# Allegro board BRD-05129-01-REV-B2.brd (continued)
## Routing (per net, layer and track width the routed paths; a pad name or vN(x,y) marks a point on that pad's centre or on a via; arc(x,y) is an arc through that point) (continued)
PMOD1_IO4_HDA14: length 59.1
  TOP w0.13: C379.1 v1(17.25,15.03) 17.28,15 J2.7
  L10_SIG w0.102: v1(9.44,56.82) 8.66,56.03 8.48,56.03 4.89,52.43 4.89,48.68 7.87,45.69 7.87,42.32 7.23,41.68 7.23,40.05 7.59,39.7 7.59,37.22 7.2,36.83 7.2,29.91 10.69,26.42 10.69,26.11 10.54,25.97 10.03,25.97 9.88,25.82 9.88,25.61 10.03,25.46 10.54,25.46 10.69,25.31 10.69,24.57 10.66,24.54 10.66,20.79 10.84,20.62 10.84,20.41 10.67,20.25 10.67,20.04 10.82,19.89 11.03,19.89 11.19,20.05 11.4,20.05 11.55,19.9 11.55,19.69 11.39,19.53 11.39,19.32 11.54,19.17 11.75,19.17 11.91,19.33 12.12,19.33 12.27,19.18 12.27,18.97 12.11,18.81 12.11,18.6 12.26,18.45 12.47,18.45 12.63,18.61 12.84,18.61 12.99,18.46 12.99,18.25 12.83,18.09 12.83,17.88 12.98,17.73 13.19,17.73 13.35,17.9 13.56,17.9 13.92,17.53 14.78,17.53 15.86,16.45 16.11,16.45 16.41,16.75 16.66,16.75 16.84,16.57 16.84,16.32 16.54,16.02 16.54,15.77 17.25,15.06 v1(17.25,15.03)
  BOTTOM w0.13: R282.2 v1(9.44,56.82)
PMOD1_IO5_HDA15: length 56.9
  L10_SIG w0.102: v1(9.44,51.23) 9.98,50.69 9.98,50.1 12.14,47.94 12.14,44.75 13.04,43.85 13.04,40.25 21.8,31.49 21.8,30.97 21.66,30.83 21.51,30.83 21.36,30.68 21.36,30.47 21.51,30.32 21.66,30.32 21.8,30.17 21.8,26.1 23.55,24.35 23.8,24.35 23.95,24.5 24.2,24.5 24.38,24.32 24.38,24.07 24.23,23.92 24.23,23.67 24.41,23.49 24.66,23.49 24.81,23.64 25.06,23.64 25.24,23.46 25.24,23.21 25.09,23.06 25.09,22.81 25.27,22.63 25.52,22.63 25.88,22.99 26.13,22.99 26.31,22.81 26.31,22.56 25.96,22.2 25.96,21.95 27.35,20.55 27.35,11.03 v1(27.86,10.52)
  BOTTOM w0.13: R275.2 C373.1 v1(27.86,10.52) 27.43,10.52 27.22,10.31 J2.2 ; R277.2 v1(9.44,51.23)
PMOD1_IO6_HDA16_CC: length 55.9
  TOP w0.13: C375.1 v1(23.67,15.03)
  L10_SIG w0.102: v1(23.67,15.03) 23.15,15.55 23.15,19.97 22.07,21.05 22.07,21.31 22.2,21.44 22.2,21.69 22.03,21.87 21.77,21.87 21.64,21.74 21.39,21.74 21.21,21.91 21.21,22.17 21.34,22.3 21.34,22.55 21.16,22.73 20.91,22.73 20.78,22.6 20.53,22.6 20.35,22.78 20.35,23.03 20.48,23.16 20.48,23.41 20.3,23.59 20.05,23.59 19.92,23.46 19.66,23.46 16.91,26.21 16.91,34.51 13.08,38.34 12.83,38.34 12.64,38.16 12.39,38.16 12.21,38.34 12.21,38.59 12.4,38.77 12.4,39.03 12.22,39.21 11.96,39.21 11.78,39.02 11.53,39.02 11.35,39.2 11.35,39.45 11.53,39.64 11.53,39.89 10.99,40.43 10.99,47.69 8.89,49.8 8.89,51.53 9.09,51.74 9.75,51.74 9.99,51.97 9.99,52.82 v1(9.42,53.39)
  BOTTOM w0.13: v1(23.67,15.03) 23.67,11.62 J2.4 ; R279.2 v1(9.42,53.39)
PMOD1_IO7_HDA17: length 56.2
  TOP w0.13: C378.1 v1(21,15.03)
  L10_SIG w0.102: v1(21,15.03) 20.53,15.5 20.53,18.55 19.88,19.21 19.88,19.46 20.03,19.62 20.03,19.87 19.86,20.05 19.6,20.05 19.44,19.89 19.19,19.89 19.01,20.07 19.01,20.32 19.17,20.48 19.17,20.73 18.99,20.91 18.74,20.91 18.58,20.75 18.33,20.75 18.15,20.93 18.15,21.18 18.31,21.34 18.31,21.6 18.13,21.77 17.88,21.77 17.72,21.62 17.47,21.62 13.36,25.73 12.8,25.73 8.18,30.34 8.18,36.15 9.34,37.31 9.34,42.26 9.12,42.49 9.12,46.93 7.35,48.7 7.35,52.4 9.44,54.49 v1(9.44,54.53)
  BOTTOM w0.13: J2.6 21.1,11.6 21.1,14.93 v1(21,15.03) ; R281.2 v1(9.44,54.53)
PMOD1_IO8_HDA18: length 57.8
  TOP w0.13: J2.8 15.97,11.62 15.97,14.14 15.92,14.19 v1(15.92,15.03) C380.1
  L10_SIG w0.102: v1(9.44,58.09) 7.87,56.51 7.53,56.51 5.88,54.86 5.88,54.34 4.24,52.7 4.24,45.92 4.44,45.72 4.44,42.06 4.14,41.75 4.14,36.29 4.01,36.17 4.01,34.26 4.62,33.65 4.62,29.18 9.4,24.39 9.4,20.64 15.01,15.03 v1(15.92,15.03)
  BOTTOM w0.13: R283.2 v1(9.44,58.09)
PMOD_3V3: length 12.8
  TOP w0.381: C238.1 v1(12.3,17.06) ; U42.1 v1(3.41,10.55) ; C376.1 v1(12.3,16.18)
  L05_SIG w0.381: J2.11 13.04,12.01 ; J2.11 11.36,12.01 ; J2.11 11.36,13.69 ; J2.11 13.04,13.69 ; J2.12 13.04,11.15 ; J2.12 11.36,11.15 ; J2.12 13.04,9.47 ; J2.12 11.36,9.47
  BOTTOM w0.381: v1(3.41,10.55) 3.38,10.52 C387.1
PMOD_PWR_EN: length 1.9
  TOP w0.381: U42.4 v1(5.31,14.94)
  BOTTOM w0.381: R167.1 5.35,14.97 v1(5.31,14.94)
PMOD_PWR_FLT_B: length 1.9
  TOP w0.381: U42.3 v1(5.31,10.55)
  BOTTOM w0.381: v1(5.31,10.55) 5.35,10.52 R166.2
PMU_RESET_OUT_B: length 34.3
  L10_SIG w0.102: v1(31.98,44.33) 32.88,44.33 33.27,43.94 35.4,43.94 36.6,42.75 37.41,42.75 38.19,41.97 38.19,41.36 38.68,40.88 38.68,33.83 33.99,29.14 J51.2
  BOTTOM w0.13: v1(31.98,44.33) 31.98,43.75 32.18,43.56 U19.16
PS_1V2: length 40.1
  TOP w0.381: v1(24.94,80.44) 24.84,80.54 v1(24.84,82.24) 24.84,83.51 26.76,85.44 v1(27.68,85.44) ; v2(25.83,90.98) 25.83,88.57 26.93,87.47 v1(27.68,87.47) ; C285.1 63.78,86.09 63.98,86.29 v1(63.98,87.07)
  BOTTOM w0.178: v1(24.84,82.24) U5.12
  BOTTOM w0.203: v1(68.4,92.63) 68.28,92.51 U43.33 ; U43.12 59.4,93.31 v1(59.14,93.57) ; U43.43 66.38,87.7 67.22,86.87 v1(68.22,86.87) ; U43.28 66.38,95.57 v1(66,95.96) ; v1(59.2,90.19) 59.51,90.51 U43.5 ; v1(59.54,95.96) 59.54,95.62 60.2,94.96 U43.15 ; U43.21 v1(63.58,95.96)
  BOTTOM w0.254: R21.1 v1(24.94,80.44) ; U43.49 v1(63.98,87.07)
  BOTTOM w0.381: C290.1 70.13,85.87 69.7,86.3 69.21,86.3 68.65,86.87 v1(68.22,86.87) ; C283.1 59.95,96.37 v1(59.54,95.96) ; C284.1 C295.1 59.15,90.24 v1(59.2,90.19) ; C292.1 63.53,96.01 v1(63.58,95.96) ; v1(66,95.96) 66.26,96.21 66.39,96.21 66.83,96.65 C289.1 ; C291.1 C296.1 69.79,93.19 68.96,93.19 v1(68.4,92.63) ; v1(59.14,93.57) 59.08,93.57 57.96,94.69 C286.1
  vias: v1(27.68,86.45)
PS_1V2_FB: length 2.8
  BOTTOM w0.203: R21.2 26.53,81.56 26.36,81.74 U5.10
  BOTTOM w0.254: R21.2 R26.1
PS_1V8: length 79.1
  TOP w0.178: v1(49.47,26.19) 49.17,25.88 U25.6
  TOP w0.254: U94.B5 v1(110,103.04) ; v1(68.37,87.9) 68.15,87.68 67.01,87.68 66.41,88.28 66.17,88.28 66.03,88.41 U98.40 ; v1(60.31,87.53) 60.31,88.13 60.85,88.66 U98.31 ; U98.25 59.55,91.76 58.79,92.52 v1(58.43,92.52) ; v1(29.59,25.38) U16.2
  TOP w0.381: v1(53.56,88.42) R543.1 R542.1 ; R545.1 59.96,83.97 v1(58.63,83.97) 58.63,84.68 R544.1 ; C623.1 C640.1 58.3,92.65 v1(58.43,92.52) ; v1(68.37,87.9) C624.1 C622.1 ; v1(60.31,87.53) 60.27,87.57 C633.1 58.89,87.57 C632.1 ; R548.1 R546.1 53.72,91.97 v1(53.6,92.1) ; R536.1 55.4,98.69 v1(55.42,98.71) ; C92.1 42.85,27.16 v1(43.21,27.52) ; v1(55.93,95.93) 56.41,95.45 R537.1 ; v1(60.11,79.46) R547.1 60.79,81.93 R541.1 ; C631.1 v1(70.13,85.04) ; U94.A5 v1(106.11,102.27)
  L05_SIG w0.508: v1(58.63,83.97) 59.29,83.31 60.76,83.31 63.18,80.9 63.18,79.22 62.57,78.61 60.96,78.61 v1(60.11,79.46)
  BOTTOM w0.178: v1(43.21,27.52) 43.52,27.22 U64.6 ; U22.2 v1(40.27,28.86) ; U22.12 37.21,29.26 v1(36.9,29.56) ; v1(37.35,30.48) 37.6,30.48 37.99,30.09 U22.13
  BOTTOM w0.254: v1(45,80.41) 44.75,80.41 44.37,80.04 U37.14 ; U37.11 42.87,80.23 v1(42.77,80.34) ; R530.1 39.29,43.09 v1(39.59,42.78) ; U37.32 v1(41.87,73.71) ; v1(32.13,36.48) R449.1 32.14,37.11 R450.1 33.88,37.11 R451.1 v1(33.89,36.46) ; v1(5.05,89.38) 4.65,88.99 U13.10 ; R448.1 v1(33.31,47.06) ; R447.1 v1(34.2,47.06) ; U37.30 v1(42.87,73.71) ; C275.1 40.13,78.79 v1(40.15,78.76) 40.2,78.71 U37.8 ; C277.1 43.18,72.52 43.87,73.21 v1(43.87,73.71) U37.28 ; R683.1 v1(117.55,90.63) ; U13.1 4.65,85.72 v1(5.05,85.32)
  BOTTOM w0.381: R48.1 5.43,82.58 v1(5.74,82.27) ; C81.1 40.3,28.89 v1(40.27,28.86) ; C612.1 57.71,76.94 ; 58.72,76.94 R522.1 59.28,76.39 ; v1(3.3,82.22) 3.65,82.57 R47.1 R49.1 ; C276.1 41.36,73.2 v1(41.87,73.71) ; R515.1 v1(112.92,108.76) ; C329.1 29.45,25.52 v1(29.59,25.38) ; R45.1 v1(40.05,25.19) ; C600.1 v1(106.11,102.27) ; R46.1 v1(1.68,92.25) ; R516.1 v1(108.74,101) ; C91.1 49.7,25.39 49.7,25.96 v1(49.47,26.19) ; R210.1 v1(44.2,70.79) ; C50.1 v1(5.63,91.23)
  vias: v1(27.17,90.45) v1(27.17,89.43) v1(27.17,88.41) v1(28.19,90.45) v1(28.19,89.43) v1(28.19,88.41) v1(29.31,19.91) v1(30.25,19.91) v1(31.16,29.51) v1(31.26,19.91) v1(32.41,19.91) v1(43.33,1.82) v1(44.62,1.82) v1(56.94,78.48) v1(56.94,77.21) v1(58.47,77.21) v1(70.58,84.25) v1(83.49,102.33) v1(83.49,101.49) v1(83.49,100.22) v1(83.49,98.95) v1(112.92,95.86) v1(113.64,96.88) v2(49.2,94.15)
PS_1V8_EN: length 1.6
  BOTTOM w0.13: U96.5 R521.2
PS_1V8_FB: length 4
  BOTTOM w0.13: R523.1 58.73,75.48 R522.2 C612.2 57.37,75.49 57.07,75.19 U96.4
PS_1V8_RS485: length 4.3
  TOP w0.381: v1(122.97,94.42) 122.9,94.35 U95.1 ; 114.52,94.62 C602.1 115,95.1
  BOTTOM w0.381: v1(114.32,94.62) 114.91,94.03 R519.1
  vias: v1(115.23,95.92)
PS_3V3: length 67.5
  TOP w0.381: v1(34.69,97.21) 34.39,96.91 C560.1 ; C64.1 v1(31.3,22.58) ; R549.1 56.83,98.35 v1(56.85,98.37) ; C574.1 31.73,100.04 v1(31.28,100.49) 30.88,100.09 C176.1 ; C589.1 6.13,65.68 v7(6.95,64.86) ; R538.1 v1(71.78,91.84) ; v1(35.69,28.4) 35.44,28.15 C53.1 ; R54.1 v1(28.45,20.86) ; R256.2 v1(34.5,25.66) ; v1(28.49,93) 28.88,93.39 C561.1 ; C559.1 v1(27.21,97.21)
  L10_SIG w0.381: J24.11 79.85,114.37 ; J24.11 78.86,114.03 ; J24.11 80.18,115.35 ; J24.11 77.88,114.37 ; J24.11 77.54,115.35 ; J24.13 69.13,114.37 ; J24.13 66.83,115.35 ; J24.13 67.16,114.37 ; J24.13 69.46,115.35 ; J24.13 68.14,114.03
  BOTTOM w0.203: U43.44 65.98,87.55 67.11,86.43 67.11,86.18 ; v1(68.35,93.47) 68.19,93.31 U43.31 ; U43.37 68.01,90.91 v1(68.23,91.13) ; U43.16 v1(61.58,95.96)
  BOTTOM w0.254: 67.11,86.18 v1(67.09,86.18) ; v1(35.44,22.81) 35.15,22.52 U15.1 ; C303.1 C298.1 60.99,86.73 v1(61.33,87.07) 61.58,87.32 U43.55 ; U38.22 v1(34.69,97.21) ; C561.1 28.88,93.39 v1(28.49,93) ; C5.1 8.81,55.02 8.81,56.38 8.62,56.58 R1.1 ; v1(31.28,100.49) 30.88,100.09 C176.1 ; v1(35.69,28.4) 35.15,27.85 U15.8 ; C559.1 v1(27.21,97.21)
  BOTTOM w0.381: R220.2 v1(71.78,87.9) ; v1(27.36,24.87) 27.61,24.61 R56.1 R55.1 ; C297.1 61.1,96.44 v1(61.58,95.96) ; 7.56,56.58 R1.1 8.12,57.13 ; 67.11,86.18 67.72,85.57 C299.1 ; R468.2 R469.2 v1(65.94,98.65) ; R429.1 v1(34.48,101.39) ; C300.1 69.95,90.52 68.99,90.52 68.38,91.13 v1(68.23,91.13) ; 60.99,75.41 R243.1 60.43,75.97 ; v1(68.35,93.47) 68.75,93.87 C304.1 ; R218.1 v1(71.78,86.88) ; 51.56,76.64 R521.1 52.12,76.09 ; R464.1 v1(36.19,91.37) ; U89.6 v7(6.95,64.86) ; R130.1 v1(37.49,93.68) ; R494.1 v1(1.84,66.46) ; R463.1 v1(37.49,92.54)
  vias: v1(5.61,58.75) v1(7.03,60.88) v1(7.03,59.86) v1(7.03,58.72) v1(7.41,57.83) v1(8.05,60.88) v1(8.05,59.86) v1(8.05,58.72) v1(9.06,60.4) v1(9.06,59.25) v1(20.67,66.01) v1(20.67,63.47) v1(21.84,66.04) v1(21.84,63.5) v1(23.11,66.04) v1(23.11,63.5) v1(25.45,47.65) v1(25.45,46.38) v1(26.72,47.65) v1(26.72,46.38) v1(27.99,47.65) v1(27.99,46.38) v1(51.74,77.72) v1(52.5,78.35) v1(52.5,77.08) v1(60.61,76.99) v1(61.37,77.63) v1(61.37,76.36) v1(71.38,98.51) v1(71.42,97.4) v2(7.29,61.9)
PS_3V3_FB: length 3.3
  TOP w0.381: R2.1 v1(7.36,55.68)
  BOTTOM w0.203: R2.1 v1(7.36,55.68)
  BOTTOM w0.381: R1.2 v1(7.36,55.68)
PS_3V3_MODE: length 4.2
  BOTTOM w0.203: U1.13 7.02,53.48 7.43,53.06 R4.2 R5.1
PS_3V3_RAMP: length 1.6
  BOTTOM w0.203: C5.2 7.25,54.83 7.05,55.03 U1.11
PS_ERROR_OUT_M2C: length 16.1
  TOP w0.127: TP38.1 9.06,64.31 v1(9.98,64.31)
  TOP w0.13: JA1.B24 v4(16.01,56.4)
  L05_SIG w0.102: v4(16.01,56.4) 15.36,55.75 12.29,55.75 11.64,56.4 11.64,57.64 11.17,58.11 11.17,59.36 10.68,59.85 10.68,63.61 v1(9.98,64.31)
PS_ERROR_STATUS_M2C: length 9.5
  TOP w0.127: TP39.1 v1(8.3,54.02)
  TOP w0.13: JA1.B25 v4(15.19,56.46)
  L12_SIG w0.102: v4(15.19,56.46) 14.54,55.82 10.84,55.82 10.06,55.05 8.86,55.05 8.3,54.49 v1(8.3,54.02)
PS_ETH_0V9: length 23.1
  TOP w0.254: U98.28 60.15,90.26 59.49,89.61 58.87,89.61 v1(58.49,89.22) ; 65.69,85.46 65.07,85.46 64.54,86 64.54,87.53 64.03,88.04 U98.36 ; v1(69.11,89.51) 69.11,89.84 68.45,90.49 67.59,90.49 67.33,90.76 U98.4
  TOP w0.381: C637.1 C627.1 69.81,89.42 69.73,89.51 v1(69.11,89.51) ; C629.1 57.95,91.76 58.25,91.46 58.29,91.46 58.45,91.3 v1(58.49,91.3) ; v1(58.49,89.22) 58.24,88.97 C636.1 57.76,90.04 C628.1 ; v2(50.85,93.26) 50.85,91.49 v1(52.5,89.84) ; C638.1 C630.1 v1(65.69,85.47)
  BOTTOM w0.381: 67.59,76.27 R6.1 68.15,75.71 ; C14.1 66.58,76.27
  vias: v1(65.81,77.76) v1(65.81,76.49) v1(67.34,76.49)
PS_ETH_0V9_EN: length 1.6
  BOTTOM w0.254: R243.2 U12.5
PS_ETH_0V9_FB: length 4.4
  BOTTOM w0.254: U12.4 66.28,74.51 C14.2 R6.2 R17.1
PS_GEM0_LED0_CA: length 8
  BOTTOM w0.13: R561.2 82.85,112.57 81.58,113.84 77.83,113.84 J24.12
PS_GEM0_LED1_CA: length 4.7
  BOTTOM w0.13: J24.14 63.56,115.35 63.17,115.74 R551.2
PS_GEM0_MDI_0_N: length 21.8
  TOP w0.089: U98.13 65.03,94.93 65.16,95.06 65.16,97.72 64.91,97.96 64.91,98.97 v3(64.64,99.24)
  L03_SIG w0.089: v3(64.64,99.24) 64.85,99.24 65.38,99.77 65.73,99.77 65.96,100 74.93,100 76.6,101.67 76.6,103.24 77.02,103.66 77.18,103.74 77.22,103.86 J24.2
PS_GEM0_MDI_0_P: length 21.8
  TOP w0.089: v3(65.42,99.24) 65.17,98.98 65.17,98.07 65.41,97.83 65.41,95.06 65.53,94.93 U98.12
  L03_SIG w0.089: v3(65.42,99.24) 65.7,99.51 65.83,99.51 66.07,99.75 75.04,99.75 76.07,100.78 76.22,100.78 76.43,100.57 76.58,100.57 76.69,100.68 76.69,100.83 76.48,101.04 76.48,101.19 76.85,101.56 76.85,103.13 77.17,103.45 77.29,103.51 77.41,103.47 J24.1
PS_GEM0_MDI_1_N: length 20.4
  TOP w0.089: U98.15 64.03,94.93 64.16,95.06 64.16,96.81 v3(63.9,97.07)
  L03_SIG w0.089: J24.6 72.75,104.94 72.94,104.75 72.94,103.89 72.73,103.68 72.01,103.68 71.48,103.16 71.48,101.43 71.09,101.04 64.33,101.04 63.78,100.48 63.78,99.08 64.16,98.7 64.16,97.33 v3(63.9,97.07)
PS_GEM0_MDI_1_P: length 20.4
  TOP w0.089: v3(64.68,97.07) 64.41,96.8 64.41,95.06 64.53,94.93 U98.14
  L03_SIG w0.089: v3(64.68,97.07) 64.41,97.34 64.41,98.8 64.03,99.18 64.03,100.38 64.44,100.78 71.2,100.78 71.74,101.32 71.74,103.05 72.11,103.42 73.86,103.42 J24.3
PS_GEM0_MDI_2_N: length 21
  TOP w0.089: J24.5 73.4,103.47 73.53,103.51 73.65,103.45 74.04,103.06 74.04,101.65 73.35,100.96 72.39,100.96 72.28,101.07 72.28,101.13 72.17,101.24 72.01,101.24 71.9,101.13 71.9,101.07 71.79,100.96 64.62,100.96 62.81,99.15 62.81,95.58 63.16,95.24 63.16,95.06 63.03,94.93 U98.17
PS_GEM0_MDI_2_P: length 21
  TOP w0.089: U98.16 63.53,94.93 63.41,95.06 63.41,95.34 63.06,95.69 63.06,99.05 64.72,100.71 73.46,100.71 74.29,101.54 74.29,103.16 73.8,103.66 73.64,103.74 73.6,103.86 J24.4
PS_GEM0_MDI_3_N: length 17.7
  TOP w0.089: U98.19 62.03,94.93 62.16,95.06 62.16,96.5 61.82,96.84 61.82,99.22 v3(61.56,99.48)
  L03_SIG w0.089: v3(61.56,99.48) 61.82,99.74 61.82,101.71 63.61,103.49 66.79,103.49 67.05,103.75 68.47,103.75 68.56,103.66 69.4,103.66 69.56,103.74 69.6,103.86 J24.8
PS_GEM0_MDI_3_P: length 17.7
  TOP w0.089: U98.18 62.53,94.93 62.41,95.06 62.41,96.61 62.07,96.95 62.07,99.21 v3(62.34,99.48)
  L03_SIG w0.089: J24.7 69.79,103.47 69.67,103.51 69.46,103.41 68.45,103.41 68.37,103.49 67.15,103.49 66.9,103.24 63.72,103.24 62.08,101.6 62.08,100.73 62.17,100.64 62.25,100.64 62.34,100.55 62.34,100.37 62.25,100.28 62.18,100.28 62.08,100.17 62.08,99.74 v3(62.34,99.48)
PS_GEM0_MDIX_MODE: length 6.9
  TOP w0.127: U98.27 59.06,90.76 58.82,90.51 58.16,90.51 57.95,90.72 56.29,90.72 55.93,91.09
  TOP w0.13: 55.93,91.09 R557.1 R546.2
PS_GEM0_PHY_CFG0: length 26.3
  TOP w0.127: v1(57.96,96.19) 58.31,96.19 60.74,93.76 U98.21
  TOP w0.13: v1(57.96,96.19) 57.73,96.42 R549.2
  L03_SIG w0.102: v1(59.29,113.78) 59.29,102.67 57.32,100.71 57.32,96.82 v1(57.96,96.19)
  BOTTOM w0.13: Q29.1 58.62,115.26 R550.1 v1(59.29,113.78) ; R549.2 57.73,96.42 v1(57.96,96.19)
PS_GEM0_PHY_CFG1: length 51.3
  TOP w0.127: v1(55.93,92.55) 55.93,91.83 56.73,91.03 58.08,91.03 58.29,90.82 58.69,90.82 59.13,91.26 U98.26
  TOP w0.13: v1(55.93,92.55) 55.79,92.68 55.47,92.68 R548.2 R559.1
  L03_SIG w0.102: v1(84.68,109.57) 84.68,106.49 74.02,95.83 74.02,91.93 73.42,91.33 71.64,91.33 70.96,90.66 69.05,90.66 68.77,90.93 68.77,91.32 68.48,91.61 67.06,91.61 65.4,93.26 61.9,93.26 61.73,93.1 58.22,93.1 57.67,92.55 v1(55.93,92.55)
  BOTTOM w0.13: Q30.1 v1(84.68,109.57)
PS_GEM0_RESET_B: length 81.2
  TOP w0.127: v1(72.99,90.8) 72.45,91.34 70.27,91.34 70.13,91.48 R538.2 69.06,91.84 68.8,92.1 68.09,92.1 67.92,92.26 U98.7
  TOP w0.13: v1(37.74,55.16) 38.12,54.78 38.12,41.97 v1(37.61,41.47)
  L05_SIG w0.102: v1(72.99,90.8) 73.23,90.56 73.23,84.79 72.14,83.7 71.91,83.7 69.44,81.22 67.86,81.22 64.12,77.48 62.87,77.48 62.3,76.91 62.3,76.37 61.31,75.38 56,75.38 55.42,74.8 52,74.8 50.65,73.45 49.43,73.45 48.04,72.07 48.04,71.62 44.67,68.25 44.22,68.25 37.74,61.76 v1(37.74,55.16)
  BOTTOM w0.13: v1(37.61,41.47) U19.29
PS_GEM0_XTAL_IN: length 9.2
  TOP w0.127: U98.9 67.12,93.26 67.56,93.7 67.56,93.79 68.14,94.37 69.5,94.37 R540.2 70.7,94.72 C644.1 71.31,94.81 71.48,94.64 73.77,94.64 74.57,95.45 X14.3
PS_GEM0_XTAL_OUT: length 6.6
  TOP w0.127: X14.1 72.19,93.82 C643.1 R540.1 69.61,94.05 68.25,94.05 67.86,93.67 67.86,93.53 67.09,92.76 U98.8
PS_POR_B: length 68
  TOP w0.13: JA1.C15 v4(14.29,50.66)
  L05_SIG w0.102: v1(29.33,40.18) 29.45,40.06 33.02,40.06 33.93,39.14 33.93,37.55 34.64,36.85 34.64,34.2 36.82,32.02 37.52,32.02 37.93,31.6 37.93,25.41 37.11,24.58 37.11,22.23 38.54,20.79 39.9,20.79 40.89,19.8 v1(40.89,18.5)
  L10_SIG w0.102: J51.1 33.06,16.71 35.97,16.71 37.76,18.5 v1(40.89,18.5) ; v4(14.29,50.66) 15.06,49.88 16.3,49.88 16.4,49.78 17.42,49.78 18.87,51.23 19.78,51.23 20.98,50.03 20.98,47.15 27.95,40.18 v1(29.33,40.18)
  BOTTOM w0.13: Q45.3 v1(40.89,18.5) ; v1(29.33,40.18) 29.7,40.18 30.22,40.7 31.36,40.7 31.74,41.07 U19.11
PS_SRST_C2M_B: length 92.1
  TOP w0.13: JA1.C16 v4(14.29,51.29) ; v1(47.93,18.59) 48.56,17.95 48.56,17.06 47.04,15.54 47.04,14.14 44.5,11.6 32.18,11.6 30.4,9.83 30.4,5.58 31.4,4.58 J3.14
  L03_SIG w0.102: v1(47.93,18.59) 46.66,18.59 45.51,19.73 45.51,20.4 J1.3
  L05_SIG w0.102: J1.3 41.02,24.89 41.02,31.47 39.44,33.04 36.81,33.04 35.55,34.3 35.55,36.32 36.83,37.6 36.83,39.01 35.63,40.2 35.63,44.75 34.92,45.46 25.12,45.46 24.49,46.09 18.12,46.09 17.72,46.48 15.79,46.48 15.59,46.68 15.59,47.77 14.73,48.64 14.73,50.85 v4(14.29,51.29)
  BOTTOM w0.13: Q47.3 v1(47.93,18.59)
PWRGD_FPD_M2C: length 41.7
  TOP w0.305: JA1.D24 v4(13.38,56.43)
  L03_SIG w0.254: v4(13.38,56.43) 12.86,55.91 12.48,55.91 12.4,55.83 12.38,55.83 12.37,55.82 11.4,55.82 11.03,56.18 8.81,56.18 7.24,54.61 7.24,48.57 4.92,46.26 4.92,41.99 3.73,40.8 3.73,38.76 4.29,38.2 4.29,35.48 4,35.2 4,31.78 4.87,30.91 4.87,28.95 6.47,27.35 6.47,25.27 v1(5.76,24.56)
  BOTTOM w0.229: Q7.1 5.61,24.4 v1(5.76,24.56)
PWRGD_LPD_M2C: length 40.6
  TOP w0.305: JA1.D25 v4(12.54,56.38)
  L03_SIG w0.254: v4(12.54,56.38) 12.53,56.38 12.46,56.45 12.13,56.45 11.13,57.45 8.92,57.45 8.11,56.64 7.39,56.64 6.44,55.69 6.44,54.92 3.43,51.91 3.43,46.53 4.29,45.66 4.29,42.25 2.82,40.78 2.82,30.11 5.7,27.22 v1(5.76,27.22)
  BOTTOM w0.229: Q17.1 5.48,26.94 v1(5.76,27.22)
PWRGD_PL_M2C: length 52.2
  TOP w0.305: JA1.D26 v4(12.5,57.07)
  L03_SIG w0.254: v4(12.5,57.07) 10.86,58.72 9.2,58.72 7.77,57.29 5.97,57.29 3.7,55.02 3.7,53.09 2.3,51.69 2.3,46.17 1.11,44.98 1.11,41.91 1.47,41.55 1.47,21.99 2.59,20.87 4.62,20.87 v1(5.89,19.6)
  BOTTOM w0.229: Q9.1 5.61,19.32 v1(5.89,19.6)
PWROFF_C2M_B: length 116.9
  TOP w0.305: JA1.B26 v4(15.19,57.1)
  TOP w0.381: J12.3 11.98,101 C207.1 11.51,99.9 11.26,99.64 8.89,99.64 7.92,98.68 7.92,84.75 10.97,81.71 10.97,66.72 v1(10.16,65.91) ; Q21.3 17.57,23.52 15.94,21.89 13.86,21.89 13.41,22.35 13.41,24.38 9.05,28.74 7.04,28.74 v1(6.02,29.76) ; v1(11.3,60.3) 11.1,60.09 11.1,43.3 9.93,42.13 7.34,42.13 v6(6.56,41.35)
  L03_SIG w0.381: v1(10.16,65.91) 11.27,64.79 11.27,60.32 v1(11.3,60.3) 12.02,59.58 17.07,59.58 17.5,59.15 17.5,58.11 17.04,57.65 15.74,57.65 v4(15.19,57.1)
  L10_SIG w0.508: v6(6.56,41.35) 6.02,40.81 6.02,37.49 6.44,37.07 6.44,34.31 6.02,33.89 v1(6.02,29.76)
  BOTTOM w0.254: v1(6.02,29.76) 5.73,29.48 Q6.1 ; U7.3 v6(6.56,41.35)
QEI_DP_A_N: length 29.1
  L12_SIG w0.089: v5(121.85,87.14) 121.59,87.41 121.59,87.93 123.24,89.58 126.41,89.58 128.06,91.23 128.06,95.93 127.44,96.56 126.09,96.56 v5(125.57,97.07)
  BOTTOM w0.089: 124.44,97.07 v5(125.57,97.07) ; v5(121.85,87.14) 121.55,86.84 121.55,86.14 R669.2 121.59,85.45 121.59,85.22 121.67,85.13 121.87,85.13 121.96,85.04 D18.2 121.96,81.8 121.59,81.43 121.59,80.99 121.84,80.74 121.84,78.96 121.35,78.47 120.58,78.47 120.44,78.33 J43.5
QEI_DP_A_P: length 29.1
  L12_SIG w0.089: v5(125.57,95.8) 126.06,96.3 126.44,96.3 126.54,96.2 126.54,96.06 126.65,95.96 126.8,95.96 126.9,96.06 126.9,96.2 127,96.3 127.33,96.3 127.81,95.83 127.81,91.34 126.31,89.84 123.13,89.84 121.33,88.04 121.33,87.49 v5(120.98,87.14)
  BOTTOM w0.089: U117.10 v5(125.57,95.8) ; v5(120.98,87.14) 121.29,86.84 121.29,86.05 R669.1 121.33,85.45 121.33,85.22 121.24,85.13 121.05,85.13 120.96,85.04 D18.1 120.96,81.76 121.33,81.39 121.33,80.89 121.59,80.63 121.59,79.06 121.25,78.72 120.54,78.72 120.44,78.81 J43.6
QEI_DP_B_N: length 17.3
  BOTTOM w0.089: J43.9 125.52,78.54 125.4,78.66 124.64,78.66 124.2,79.1 124.2,81.67 124.1,81.78 123.9,81.78 123.81,81.87 D17.2 123.81,84.57 124.19,84.95 124.19,85.38 R670.2 124.17,86.01 124.17,87.03 124.54,87.39 125.67,87.39 126.09,87.82 126.09,89.63 125.76,89.96 125.28,89.96 124.78,89.45 U117.15
QEI_DP_B_P: length 17.2
  BOTTOM w0.089: U117.14 124.79,90.72 125.29,90.22 125.87,90.22 126.35,89.74 126.35,87.71 125.77,87.14 124.65,87.14 124.43,86.92 124.43,86.04 R670.1 124.44,85.38 124.44,84.95 124.81,84.58 D17.1 124.81,81.87 124.72,81.78 124.59,81.78 124.45,81.64 124.45,79.2 124.74,78.91 125.43,78.91 125.52,79.01 J43.10
QEI_DP_I_N: length 15.1
  BOTTOM w0.089: U117.1 118.83,88.18 118.32,88.69 118.05,88.69 117.81,88.45 117.81,87.73 118.79,86.75 118.79,86.35 R671.2 118.79,85.7 118.79,85.35 118.88,85.26 119.08,85.26 119.16,85.17 D19.2 119.16,81.83 118.79,81.45 118.79,81.13 119.32,80.6 119.32,79.01 118.96,78.64 118.04,78.64 117.9,78.51 J43.3
QEI_DP_I_P: length 15.1
  BOTTOM w0.089: U117.2 118.84,89.45 118.34,88.95 117.95,88.95 117.56,88.55 117.56,87.62 118.54,86.64 118.54,86.35 R671.1 118.54,85.7 118.54,85.35 118.45,85.26 118.25,85.26 118.16,85.17 D19.1 118.16,84.54 118.16,81.78 118.54,81.4 118.54,81.03 119.07,80.5 119.07,79.12 118.85,78.9 118.06,78.9 117.9,79.06 J43.4
QEI_LOW_REF: length 2.9
  TOP w0.127: v1(118.07,95.8) R667.2 116.76,95.8 116.76,95.8 R668.1
  BOTTOM w0.13: U117.7 v1(118.07,95.8)
QEI_SE_A: length 9
  TOP w0.127: v1(128.68,72.17) 128.56,72.17 128.33,71.94 U116.4
  TOP w0.13: v1(128.68,72.17) 129.13,72.17 R665.2
  BOTTOM w0.13: v1(128.68,72.17) 129.06,72.17 129.3,71.94 D16.2 132.63,71.94 133.63,70.94 J42.3
QEI_SE_B: length 14.2
  TOP w0.127: U116.5 127.66,72.69 128.57,72.69 129.51,73.63 129.51,75.26 128.58,76.19 v1(128.58,77.02)
  TOP w0.13: v1(128.58,77.02) 128.59,77.01 R666.2
  BOTTOM w0.13: J42.5 134.12,77.02 D15.2 v1(128.58,77.02)
QEI_SE_I: length 9.6
  TOP w0.13: R664.2 129.09,70.94 v1(128.71,70.56) 128.62,70.64 U116.2
  BOTTOM w0.13: v1(128.71,70.56) 129.09,70.94 D16.1 132.58,70.94 J42.2
QEI_SEL: length 55.4
  TOP w0.127: v1(120.44,74.21) 120.77,73.89 U116.8
  L03_SIG w0.102: v1(120.44,74.21) 121.35,75.13 121.35,76.45 121.69,76.78 121.69,81.05 123.44,82.8 123.44,91.12 v1(125.59,93.26)
  L12_SIG w0.102: J44.1 96.07,72.22 97.15,71.14 107.43,71.14 110.5,74.21 v1(120.44,74.21)
  BOTTOM w0.13: R672.2 v1(125.59,93.26) U117.12
SD_CTRLR_RESET_B: length 65.8
  L05_SIG w0.102: v1(33.4,101.39) 33.4,94.69 32.89,94.18 32.89,89.73 29.1,85.95 29.1,80.49 v1(28.55,79.93)
  L10_SIG w0.102: v1(28.55,79.93) 28.62,79.85 28.62,60.83 v1(34.82,54.63)
  BOTTOM w0.127: U38.18 32.88,99.84 R429.2 33.58,101.21 v1(33.4,101.39)
  BOTTOM w0.13: U19.18 33.09,44.13 32.64,44.58 32.64,52.45 v1(34.82,54.63)
SDIO_CD_B: length 31.4
  TOP w0.13: v1(31.29,102.18) 31.96,102.18 32.09,102.05 32.09,101.52 31.96,101.38 30.47,101.38 30.34,101.52 J11.13
  L03_SIG w0.102: v1(31.29,102.18) 31.29,103.58 31.14,103.73 30.42,103.73 30.27,103.88 30.27,104.09 30.42,104.24 31.14,104.24 31.29,104.39 31.29,105.01 31.39,105.11 31.79,105.11 31.97,104.94 31.97,102.4 32.13,102.24 32.34,102.24 32.48,102.37 32.48,105.03 32.6,105.15 33.05,105.15 33.18,105.03 33.18,102.2 32.82,101.84 32.82,101.16 33.63,100.34 33.63,96.07 v1(34.92,94.79)
  BOTTOM w0.13: U38.26 34.49,95.21 v1(34.92,94.79) 34.92,94.2 35.44,93.68 R130.2
SDIO_CLK: length 1.6
  BOTTOM w0.13: R249.1 U38.9
SDIO_CLK_R: length 29.2
  TOP w0.13: v1(31.8,109.14) 32.64,109.98 J11.5
  L12_SIG w0.102: v1(25.61,99.44) 26.47,100.3 26.92,100.3 27.59,100.97 27.59,104.34 27.44,104.49 26.39,104.49 26.25,104.64 26.25,104.85 26.39,105 27.44,105 27.59,105.15 27.59,105.36 27.44,105.51 26.39,105.51 26.25,105.66 26.25,105.87 26.39,106.02 27.44,106.02 27.59,106.17 27.59,106.38 27.44,106.53 26.39,106.53 26.25,106.67 26.25,106.88 26.39,107.03 27.44,107.03 27.59,107.18 27.59,107.56 28.02,107.99 30.65,107.99 v1(31.8,109.14)
  BOTTOM w0.13: R249.2 v1(25.61,99.44) ; v1(31.8,109.14) 31.31,108.65 U82.7
SDIO_CMD: length 2.2
  BOTTOM w0.13: U38.11 29.38,99.99 29.1,100.27 28.68,100.27 28.38,100.58 R248.1
SDIO_CMD_R: length 28.2
  TOP w0.13: v1(30.81,109.18) 30.44,109.55 J11.3
  L12_SIG w0.102: v1(27.04,101.46) 25.62,102.88 25.62,103.11 25.47,103.26 24.9,103.26 24.75,103.41 24.75,103.62 24.9,103.76 25.47,103.76 25.62,103.91 25.62,104.12 25.47,104.27 24.9,104.27 24.75,104.42 24.75,104.63 24.9,104.78 25.47,104.78 25.62,104.93 25.62,105.14 25.47,105.29 24.9,105.29 24.75,105.44 24.75,105.65 24.9,105.8 25.47,105.8 25.62,105.95 25.62,106.16 25.47,106.3 24.9,106.3 24.75,106.45 24.75,106.66 24.9,106.81 25.47,106.81 25.62,106.96 25.62,107.17 25.47,107.32 24.9,107.32 24.75,107.47 24.75,107.68 24.9,107.83 25.47,107.83 25.62,107.98 25.62,108.41 26.87,109.67 30.32,109.67 v1(30.81,109.18)
  BOTTOM w0.13: R248.2 v1(27.04,101.46) ; U82.6 v1(30.81,109.18)
SDIO_DATA0: length 2
  BOTTOM w0.13: R250.1 U38.5
SDIO_DATA0_R: length 28.6
  TOP w0.13: J11.7 34.84,110.79 31.8,107.74 v1(31.8,105.71)
  L12_SIG w0.102: v1(24.41,96.71) 25.52,97.83 25.52,98.01 27.46,99.94 28.11,99.94 28.95,100.78 28.95,106.54 29.22,106.81 31.63,106.81 31.8,106.64 v1(31.8,105.71)
  BOTTOM w0.13: v1(31.8,105.71) 31.31,106.2 U82.1 ; R250.2 v1(24.41,96.71)
SDIO_DATA1: length 2.2
  BOTTOM w0.13: R251.1 26.64,96.21 U38.4
SDIO_DATA1_R: length 28.7
  TOP w0.13: v1(30.81,105.7) 31.36,105.14 32.58,105.14 33.54,106.11 33.54,108.6 35.94,111 J11.8
  L12_SIG w0.102: v1(24.41,95.7) 26.01,97.3 26.01,97.81 27.5,99.31 29.16,99.31 30.64,100.79 30.64,105.54 v1(30.81,105.7)
  BOTTOM w0.13: U82.2 v1(30.81,105.7) ; R251.2 v1(24.41,95.7)
SDIO_DATA2: length 2.5
  BOTTOM w0.13: U38.25 34.88,95.71 35.77,94.83 R252.1
SDIO_DATA2_R: length 29.5
  TOP w0.13: J11.1 28.24,106.55 v1(29.76,105.02)
  L03_SIG w0.102: v1(29.76,105.02) 29.76,102.67 33.15,99.29 33.15,95.39 34.38,94.16 36.04,94.16 36.71,94.83 v1(37.49,94.83)
  BOTTOM w0.13: U82.3 30.31,105.56 v1(29.76,105.02) ; R252.2 v1(37.49,94.83)
SDIO_DATA3: length 2.4
  BOTTOM w0.13: R253.1 35.77,95.97 35.03,96.71 U38.23
SDIO_DATA3_R: length 28.5
  TOP w0.13: v1(29.7,108.95) 29.34,109.31 J11.2
  L03_SIG w0.102: v1(37.49,95.97) 36.74,96.72 36.4,96.72 36.25,96.57 36.25,95.51 36.1,95.36 35.89,95.36 35.75,95.51 35.75,96.57 35.6,96.72 34.44,96.72 34.12,97.04 34.12,100.54 33.97,100.69 33.97,104.99 31.21,107.74 30.22,107.74 29.7,108.26 v1(29.7,108.95)
  BOTTOM w0.13: R253.2 v1(37.49,95.97) ; U82.5 30.31,108.35 v1(29.7,108.95)
SDIO_SCK: length 4.5
  BOTTOM w0.13: U38.31 31.38,93.38 32.15,92.61 33.3,92.61 R464.2
SDIO_SDA: length 3.2
  BOTTOM w0.13: U38.27 33.99,94.71 34.44,94.27 34.44,93.87 35.77,92.54 R463.2
SDIO_VDD: length 7.2
  TOP w0.381: C558.1 34.3,97.71 34.75,98.17 v1(35.07,98.17)
  BOTTOM w0.279: v6(32.57,107.45) U82.8 ; v1(35.07,98.17) 34.75,98.17 34.3,97.71 C558.1
  BOTTOM w0.381: C565.1 33.39,107.45 v6(32.57,107.45) ; C557.1 v1(31.25,111.35) ; C369.1 v1(31.25,112.37) ; R462.1 v1(31.25,110.47)
SDIO_VDD18: length 1.9
  BOTTOM w0.254: C175.1 30.38,100.9 U38.13
SDIO_VDD18PLL: length 1.8
  TOP w0.381: C562.1 v1(29.88,93.03)
  BOTTOM w0.254: C562.1 v1(29.88,93.03)
SDIO_WP: length 4.2
  TOP w0.13: v1(33.87,93.15) 33.11,93.15 32.87,93.39 R465.1
  BOTTOM w0.13: U38.30 31.88,93.49 32.23,93.15 v1(33.87,93.15)
SDIO_XTAL1: length 4.8
  BOTTOM w0.127: U38.33 30.38,91.94 R466.1 30.09,91.66 C563.1 X11.3
SDIO_XTAL2: length 6.9
  BOTTOM w0.127: X11.1 32.22,87.6 31.08,88.73 C564.1 R466.2 30.88,91.95 U38.32
SOM240_1_C45_NC: length 0.4
  TOP w0.13: JA1.C45 v4(14.29,69.16)
SOM240_1_D46_NC: length 0.4
  TOP w0.13: JA1.D46 v4(12.65,69.8)
SOM_5V0: length 9.2
  TOP w0.254: JA1.C59 v7(14.26,78.33) ; JA1.D60 v7(12.67,78.96) ; JA1.B60 v7(15.97,78.96) ; JA1.A59 v7(16.8,78.33) ; JA1.A60 v7(16.8,78.96) ; JA1.C60 v7(14.26,78.96)
  TOP w0.381: C324.1 v1(7.25,80.22) ; C323.1 v1(9.7,80.22)
  BOTTOM w0.381: U14.15 v8(5.59,78.67) ; U14.14 v8(4.94,78.67) ; C353.1 v1(9.09,75.56) ; U14.16 v8(6.24,78.67) ; C354.1 9.13,78.3 v1(9.49,77.94)
  vias: v8(4.94,79.68) v8(5.59,79.68) v8(6.24,79.68)
TRQ_CS_B: length 25
  L05_SIG w0.102: v1(96.11,15.49) 96.11,16.2 96.66,16.75 96.66,19.62 96.26,20.01 82.47,20.01 81.23,18.77 81.23,17.8 v1(82.15,16.88)
  BOTTOM w0.13: U119.3 v1(96.11,15.49) ; v1(82.15,16.88) U120.9
TRQ_REFIN_N: length 5.3
  BOTTOM w0.089: C776.1 R675.2 85.01,13.04 C774.2 R674.2 87.23,12.72 88,12.72 88.16,12.89 U119.10
TRQ_REFIN_P: length 5.4
  BOTTOM w0.089: U119.9 88.16,12.24 87.93,12.47 87.24,12.47 R674.1 C774.1 85.01,12.14 R673.2 84.95,11.16 C775.1
TRQ_SCLK: length 18.3
  L05_SIG w0.102: v1(81.96,18.31) 82.43,18.78 94.9,18.78 95.14,18.54 95.14,18.11 v1(96.19,17.06)
  BOTTOM w0.13: v1(96.19,17.06) 95.91,16.79 U119.1 ; v1(81.96,18.31) 81.96,17.92 81.31,17.28 U120.8
TRQ_SDI: length 4.2
  BOTTOM w0.13: U118.9 86.09,17 86.53,17.45 87.8,17.45 88.46,16.79 U119.16
TRQ_SDO: length 5.6
  L05_SIG w0.102: v1(87.55,16.94) 86.66,16.94 85.85,17.75 v1(85.85,18.24)
  BOTTOM w0.13: v1(85.85,18.24) 85.85,17.62 85.63,17.4 U118.8 ; v1(87.55,16.94) 87.87,16.62 87.87,16.49 88.22,16.14 U119.15
TRQ_SNS_N: length 15.9
  TOP w0.254: v1(103.29,14.14) 103.05,13.9 103.05,13.37 102.55,12.86 101.14,12.86 100.34,13.66 99.74,13.66 v1(99.41,13.34)
  BOTTOM w0.254: v1(99.41,13.34) 99.1,13.64 98.7,13.64 R677.1 ; v1(103.29,14.14) D20.2 103.29,12.53 103.74,12.08 103.74,10.53 103.1,9.89 103.1,7.28 103.22,7.15 J45.4
TRQ_SNS_P: length 15.1
  TOP w0.254: v1(102.29,14.14) 102.54,13.89 102.54,13.58 102.34,13.37 101.35,13.37 100.55,14.17 99.7,14.17 v1(99.41,14.46)
  BOTTOM w0.254: R676.1 98.68,14.15 99.1,14.15 v1(99.41,14.46) ; v1(102.29,14.14) D20.1 102.29,12.53 101.84,12.08 101.84,10.64 102.59,9.89 102.59,7.28 102.46,7.15 J45.3
TRQ_SNS_R_N: length 3.8
  BOTTOM w0.254: C782.1 R677.2 C779.2 96.6,13.54 U119.6
TRQ_SNS_R_P: length 3.8
  BOTTOM w0.254: U119.5 96.54,14.19 C779.1 R676.2 C781.1
TS_CLK: length 2.1
  BOTTOM w0.13: TP40.1 96.1,16.3 95.93,16.14 U119.2
USB0_ATEST: length 3.5
  BOTTOM w0.13: R222.1 62,85.5 62.78,86.27 U43.52
USB0_CFG_BC_EN: length 3.3
  BOTTOM w0.13: R219.1 69.72,89.02 68.76,89.02 68.32,89.46 68.03,89.46 67.78,89.71 U43.40
USB0_CFG_NON_REM: length 3.5
  BOTTOM w0.13: U43.41 67.74,89.31 68.76,88.29 69.74,88.29 70.13,87.9 R220.1
USB0_D1_N: length 44.1
  L12_SIG w0.109: v5(54.37,87.58) 54.68,87.89 54.68,88.59 54.36,88.92 51.21,88.92 49.25,90.88 43.71,90.88 42.06,89.23 35.58,89.23 34.51,90.29 29.3,90.29 27.44,92.15 26.66,92.15 26.31,92.5 26.31,93.34 v5(26.04,93.61)
  BOTTOM w0.109: v5(26.04,93.61) 26.31,93.88 26.31,94.85 27.06,95.59 27.58,95.59 27.7,95.71 U38.3 ; U43.2 59.68,89.31 59.6,89.24 59.22,89.24 58.54,88.56 54.89,88.56 54.62,88.28 54.62,87.83 v5(54.37,87.58)
USB0_D1_P: length 44.1
  L12_SIG w0.109: v5(55.24,87.58) 54.94,87.89 54.94,88.7 54.46,89.17 51.31,89.17 49.35,91.13 43.61,91.13 41.95,89.48 35.68,89.48 34.62,90.55 29.4,90.55 28.44,91.5 28.44,91.69 28.64,91.89 28.64,92.07 28.51,92.2 28.33,92.2 28.13,92 27.94,92 27.55,92.4 26.77,92.4 26.57,92.6 26.57,93.33 v5(26.84,93.6)
  BOTTOM w0.109: v5(26.84,93.6) 26.56,93.88 26.56,94.74 27.16,95.34 27.59,95.34 27.72,95.21 U38.2 ; U43.1 59.68,88.91 59.6,88.98 59.32,88.98 58.64,88.3 55,88.3 54.87,88.18 54.87,87.96 v5(55.24,87.58)
USB0_D2_N: length 42.8
  L03_SIG w0.109: v1(46.78,99.7) 47.06,99.97 47.06,100.91 46.38,101.59 46.38,102.84 47.21,103.68 47.21,104.17 47.56,104.51 47.95,104.78 48.37,104.95 48.7,104.95 48.93,104.85 49.21,104.67 49.64,104.24 49.64,103.93 49.75,103.82 U44.11
  L12_SIG w0.109: v5(54.37,89.92) 54.68,90.23 54.68,90.34 54.57,90.45 51.35,90.45 49.73,92.06 44.42,92.06 41.91,94.58 41.91,97.07 43.12,98.29 46.83,98.29 47.06,98.52 47.06,99.43 v1(46.78,99.7)
  BOTTOM w0.109: U43.9 59.68,92.11 59.6,92.04 55.56,92.04 54.71,91.18 54.71,90.25 v5(54.37,89.92) ; v1(46.78,99.7) 47.04,99.44 47.04,99.04 46.92,98.92 X6.1
USB0_D2_P: length 42.8
  L03_SIG w0.109: v1(47.58,99.7) 47.31,99.97 47.31,101.02 46.63,101.7 46.63,102.74 47.47,103.58 47.47,104.06 47.72,104.31 48.07,104.55 48.42,104.69 48.65,104.69 48.81,104.63 49.04,104.47 49.39,104.13 49.39,103.9 49.31,103.82 U44.12
  L12_SIG w0.109: v1(47.58,99.7) 47.31,99.43 47.31,98.41 46.93,98.04 46.37,98.04 46.24,97.9 46.24,97.69 46.11,97.56 45.93,97.56 45.8,97.69 45.8,97.9 45.66,98.04 45.48,98.04 45.35,97.9 45.35,97.72 45.21,97.58 45.03,97.58 44.9,97.71 44.9,97.9 44.77,98.04 43.23,98.04 42.16,96.97 42.16,94.69 44.53,92.32 49.84,92.32 51.46,90.7 54.68,90.7 54.94,90.44 54.94,90.23 v5(55.25,89.92)
  BOTTOM w0.109: U43.8 59.68,91.71 59.6,91.78 55.67,91.78 54.96,91.08 54.96,90.2 v5(55.25,89.92) ; X6.2 47.42,98.92 47.29,99.04 47.29,99.41 v1(47.58,99.7)
USB0_D3_N: length 39.9
  L03_SIG w0.109: v1(49.09,99.7) 49.37,99.97 49.37,100.45 49.75,100.83 51.76,100.83 52.4,101.47 52.4,102.81 51.79,103.42 51.79,104.42 52.4,105.02 52.4,105.89 51.63,106.65 51.63,107.51 51.08,108.07 50.08,108.07 49.64,107.63 49.64,107.13 49.75,107.02 U44.2
  L12_SIG w0.109: v1(49.09,99.7) 49.37,99.43 49.37,98.91 49.7,98.57 50.8,98.57 51.05,98.83 54.18,98.83 56.36,101.01 60.6,101.01 60.73,100.88 60.73,100.59 60.86,100.46 61.05,100.46 61.18,100.59 61.18,100.88 61.31,101.01 62.42,101.01 v5(62.78,100.65)
  BOTTOM w0.109: v1(49.09,99.7) 49.35,99.44 49.35,99.04 49.23,98.92 X5.1 ; v5(62.78,100.65) 62.47,100.96 62.12,100.96 61.83,100.66 61.83,99 62.03,98.79 62.03,96.55 62.31,96.27 62.31,95.69 62.38,95.61 U43.18
USB0_D3_P: length 40
  L03_SIG w0.109: v1(49.9,99.7) 49.62,99.97 49.62,100.34 49.86,100.58 51.86,100.58 52.65,101.37 52.65,102.92 52.04,103.53 52.04,104.31 52.65,104.92 52.65,105.99 51.89,106.76 51.89,107.62 51.18,108.33 49.98,108.33 49.39,107.73 49.39,107.13 49.27,107.02 U44.3
  L12_SIG w0.109: v1(49.9,99.7) 49.62,99.43 49.62,99.01 49.81,98.83 50.69,98.83 50.95,99.08 54.07,99.08 56.26,101.26 62.53,101.26 v5(62.78,101.52)
  BOTTOM w0.109: v1(49.9,99.7) 49.61,99.41 49.61,99.04 49.73,98.92 X5.2 ; U43.17 61.98,95.61 62.06,95.69 62.06,96.17 61.78,96.45 61.78,98.69 61.57,98.89 61.57,100.77 62.02,101.21 62.47,101.21 v5(62.78,101.52)
USB0_HUB_RESET_B: length 84.3
  TOP w0.127: v1(69.01,73.81) 70.02,74.82 70.02,82.55 v1(70.63,83.16)
  TOP w0.13: v1(36.55,55.8) 36.78,55.57 36.78,46.83 35.51,45.56 35.51,39.28 v1(36.01,38.78)
  L10_SIG w0.102: v1(36.55,55.8) 38.33,57.59 40.77,57.59 42.12,58.94 42.12,64.71 48.33,70.91 51.27,70.91 52.07,71.71 56.66,71.71 58.25,73.3 60.26,73.3 60.95,72.61 67.81,72.61 v1(69.01,73.81)
  BOTTOM w0.13: v1(70.63,83.16) 71.75,84.28 71.75,85.06 72.28,85.59 72.28,87.07 71.97,87.38 70.63,87.38 R218.2 69.68,86.88 69.17,87.4 68.09,87.4 67.71,87.78 67.71,88.75 67.55,88.91 U43.42 ; v1(36.01,38.78) 36.01,39.11 35.49,39.62 U19.1
USB0_PHY_RESET_B: length 39.1
  TOP w0.13: v1(36.98,57.58) 37.21,57.35 37.21,52.73 37.59,52.35 37.59,42.79 v1(36.76,41.96)
  L10_SIG w0.102: v1(44.24,69.64) 41.4,66.8 41.4,59.39 40.53,58.52 37.92,58.52 v1(36.98,57.58)
  BOTTOM w0.13: U19.28 36.66,41.87 v1(36.76,41.96) ; v1(44.24,69.64) 44.75,70.15 44.75,72.18 44.45,72.49 R210.2 44.2,72.93 44.37,73.1 U37.27
USB0_PRT_CTL2: length 55.3
  L03_SIG w0.102: v1(38.65,90.09) 39.22,90.09 40.36,91.23 40.36,91.38 41.22,92.25 41.93,92.25 43.1,93.42 49.7,93.42 50.26,93.98 52.35,93.98 53.04,93.28 57.62,93.28 58.42,94.08 59.77,94.08 60.09,93.77 65.58,93.77 67.26,92.1 68.99,92.1 69.05,92.04 70.63,92.04 70.89,92.31 71.98,92.31 72.47,91.82 v1(73.22,91.82)
  L05_SIG w0.102: v1(38.65,90.09) 39.17,90.61 39.17,91.77 40.87,93.47 40.87,95.89 v1(41.12,96.13)
  BOTTOM w0.127: v1(41.12,96.13) 40.52,96.74 U45.8 ; U45.3 39.22,91.67 39.11,91.56 39.11,90.55 v1(38.65,90.09)
  BOTTOM w0.13: v1(73.22,91.82) 72.75,91.34 69.74,91.34 69.37,91.71 U43.35
USB0_PRT_CTL3: length 44.7
  L03_SIG w0.102: v1(69.24,92.51) 69.24,93.26 68.2,94.3 60.54,94.3 60.28,94.56 57.25,94.56 57.03,94.34 54.47,94.34 53.23,95.58 47.18,95.58 45.67,94.06 41.9,94.06 39.57,91.74 39.07,91.74 v1(38.57,91.23)
  L05_SIG w0.102: v1(37.86,97.07) 38.17,96.77 38.17,91.63 v1(38.57,91.23)
  BOTTOM w0.127: U45.5 v1(37.86,97.07) ; v1(38.57,91.23) U45.4
  BOTTOM w0.13: U43.34 67.94,92.11 68.03,92.03 68.76,92.03 v1(69.24,92.51)
USB0_RBIAS: length 2.5
  BOTTOM w0.13: U43.56 59.98,88.06 59.49,87.57 R221.1
USB0_SSRX2_N: length 33.8
  L12_SIG w0.109: v5(59.02,97.93) 58.71,97.62 58.71,97.4 58.15,96.83 51.82,96.83 50.14,95.14 49.15,95.14 47.16,93.16 44.76,93.16 43.74,94.18 43.74,95.99 v5(43.46,96.26)
  BOTTOM w0.109: U44.14 46.27,102.32 46.39,102.21 46.39,101.86 45.79,101.27 44.88,101.27 43.75,100.14 43.75,99.06 43.62,98.93 U66.1 U66.10 43.62,97.25 43.75,97.12 43.75,96.55 v5(43.46,96.26) ; U43.14 59.63,94.11 58.96,94.79 58.96,96.5 58.72,96.74 58.72,97.63 v5(59.02,97.93)
USB0_SSRX2_P: length 33.8
  L12_SIG w0.109: v5(58.15,97.93) 58.46,97.62 58.46,97.5 58.04,97.08 51.72,97.08 50.03,95.4 49.04,95.4 47.06,93.41 44.86,93.41 43.99,94.28 43.99,94.79 44.12,94.93 44.2,94.93 44.33,95.06 44.33,95.24 44.2,95.37 44.12,95.37 43.99,95.5 43.99,95.99 v5(44.26,96.26)
  BOTTOM w0.109: U43.13 59.68,93.71 58.71,94.68 58.71,96.4 58.47,96.64 58.47,97.61 v5(58.15,97.93) ; U44.15 46.75,102.32 46.64,102.21 46.64,101.76 45.9,101.01 44.98,101.01 44,100.03 44,99.06 44.12,98.93 U66.2 U66.9 44.12,97.25 44,97.12 44,96.53 v5(44.26,96.26)
USB0_SSRX3_N: length 42.8
  L12_SIG w0.109: v5(44.96,95.65) 45.23,95.38 45.23,94.99 45.64,94.59 46.89,94.59 48.74,96.44 48.74,97.2 49,97.46 50.9,97.46 51.36,97.91 55.72,97.91 57.11,99.3 61.44,99.3 62.01,99.87 63.12,99.87 63.55,100.3 63.55,100.83 63.69,100.97 63.98,100.97 v5(64.31,100.65) ; U44.5 46.27,105.52 46.39,105.41 46.39,104.88 47.11,104.16 47.11,103.63 46.38,102.89 46.38,101.85 45.21,100.68 45.21,100.16 v5(44.97,99.92)
  BOTTOM w0.109: U43.23 64.38,95.61 64.33,95.67 64.33,99.45 63.69,100.09 63.69,100.9 63.81,101.01 63.94,101.01 v5(64.31,100.65) ; v5(44.96,95.65) 45.12,95.8 45.25,96.12 45.25,97.12 45.12,97.25 U66.7 U66.4 45.12,98.93 45.25,99.06 45.25,99.65 v5(44.97,99.92)
USB0_SSRX3_P: length 42.8
  L12_SIG w0.109: U44.6 46.75,105.52 46.64,105.41 46.64,104.99 47.37,104.26 47.37,103.53 46.63,102.79 46.63,101.74 45.47,100.58 45.47,100.23 v5(45.77,99.92) ; v5(64.31,101.52) 64.02,101.23 63.58,101.23 63.29,100.94 63.29,100.41 63.01,100.12 61.9,100.12 61.34,99.56 57,99.56 55.61,98.17 51.25,98.17 50.8,97.71 48.89,97.71 48.48,97.3 48.48,96.54 46.79,94.84 45.74,94.84 45.49,95.1 45.49,95.37 v5(45.76,95.65)
  BOTTOM w0.109: v5(45.76,95.65) 45.5,95.92 45.5,97.12 45.62,97.25 U66.6 U66.5 45.62,98.93 45.5,99.06 45.5,99.65 v5(45.77,99.92) ; v5(64.31,101.52) 64.05,101.27 63.7,101.27 63.44,101 63.44,99.99 64.08,99.35 64.08,95.71 63.98,95.61 U43.22
USB0_SSTX2_C_N: length 6.5
  BOTTOM w0.109: U44.17 52.27,102.32 52.39,102.21 52.39,101.45 53.48,100.36 53.48,99.37 53.36,99.25 U67.4 U67.7 53.36,97.26 C280.1
USB0_SSTX2_C_P: length 6.6
  BOTTOM w0.109: C282.1 53.86,97.46 U67.6 U67.5 53.86,99.25 53.73,99.37 53.73,100.46 52.64,101.56 52.64,102.21 52.75,102.32 U44.18
USB0_SSTX2_N: length 13.1
  L12_SIG w0.109: v5(52.85,93.55) 53.16,93.24 53.87,93.24 54.2,93.57 54.2,94.23 53.58,94.84 53.58,95.32 v5(53.27,95.63)
  BOTTOM w0.109: v5(52.85,93.55) 53.16,93.24 54.06,93.24 54.19,93.37 54.19,93.51 54.33,93.64 54.52,93.64 54.65,93.51 54.65,93.37 54.78,93.24 55.6,93.24 55.75,93.39 58.61,93.39 59.17,92.83 59.6,92.83 59.68,92.91 U43.11 ; C280.2 v5(53.27,95.63)
USB0_SSTX2_P: length 13
  L12_SIG w0.109: v5(54.16,95.63) 53.84,95.32 53.84,94.95 54.45,94.33 54.45,93.46 53.98,92.99 53.16,92.99 v5(52.85,92.68)
  BOTTOM w0.109: U43.10 59.68,92.51 59.61,92.58 59.06,92.58 58.51,93.14 55.85,93.14 55.7,92.99 53.16,92.99 v5(52.85,92.68) ; C282.2 v5(54.16,95.63)
USB0_SSTX3_C_N: length 10.3
  L12_SIG w0.109: U44.8 52.27,105.52 52.39,105.41 52.39,104.82 51.79,104.22 51.79,103.45 52.39,102.85 52.39,101.39 51.98,100.98 51.98,100.6 v5(51.7,100.32)
  BOTTOM w0.109: v5(51.7,100.32) 51.98,100.03 51.98,99.37 51.86,99.25 U67.1 U67.10 51.86,97.51 C279.2
USB0_SSTX3_C_P: length 10.1
  L12_SIG w0.109: U44.9 52.75,105.52 52.64,105.41 52.64,104.71 52.04,104.11 52.04,103.55 52.64,102.95 52.64,101.28 52.23,100.87 52.23,100.6 v5(52.51,100.32)
  BOTTOM w0.109: C281.2 52.36,97.18 U67.9 U67.2 52.36,99.25 52.23,99.37 52.23,100.04 v5(52.51,100.32)
USB0_SSTX3_N: length 26.1
  L12_SIG w0.109: v5(63.2,99.31) 62.89,99 62.89,97.74 62.45,97.3 59.96,97.3 58.69,96.02 58.69,95.34 57.59,94.24 57.59,93.14 56.17,91.72 55.14,91.72 54.8,91.37 52.23,91.37 51.43,92.17 51.43,94.59 51.81,94.97 51.81,95.3 v5(51.5,95.61)
  BOTTOM w0.109: U43.20 63.18,95.61 63.11,95.69 63.11,95.76 63.11,95.76 63.11,96.41 62.89,96.63 62.89,99 v5(63.2,99.31) ; C279.1 v5(51.5,95.61)
USB0_SSTX3_P: length 26.3
  L12_SIG w0.109: v5(52.39,95.61) 52.07,95.3 52.07,94.86 51.69,94.48 51.69,92.28 52.34,91.63 54.69,91.63 55.04,91.97 56.06,91.97 57.34,93.24 57.34,94.35 58.43,95.44 58.43,96.13 59.86,97.56 61.32,97.56 61.46,97.69 61.46,98.07 61.59,98.2 61.77,98.2 61.9,98.07 61.9,97.69 62.03,97.56 62.34,97.56 62.64,97.85 62.64,99 v5(62.33,99.31)
  BOTTOM w0.109: v5(62.33,99.31) 62.64,99 62.64,96.53 62.86,96.31 62.86,95.69 62.78,95.61 U43.19 ; C281.1 v5(52.39,95.61)
USB0_USB3320_D_N: length 29.2
  L03_SIG w0.109: v1(65.19,86.78) 65.42,87.02 65.42,87.3 64.99,87.73 63.4,87.73 63.27,87.6 63.27,87.53 63.14,87.4 62.94,87.4 62.84,87.5 62.84,87.6 62.71,87.73 61.26,87.73 60.86,88.12 56.93,88.12 56.43,87.61 54.24,87.61 49.4,82.77 47.62,82.77 47.44,82.59 47.44,81.79 v6(47.74,81.49)
  BOTTOM w0.109: U43.46 65.18,87.58 65.41,87.35 65.41,87 v1(65.19,86.78) ; v6(47.74,81.49) 47.43,81.19 47.43,78.26 47.01,77.84 46.74,77.84 46.62,77.71 U37.19
USB0_USB3320_D_P: length 29.2
  L03_SIG w0.109: v6(46.92,81.49) 47.19,81.76 47.19,82.7 47.52,83.03 49.29,83.03 54.13,87.87 56.32,87.87 56.83,88.38 60.97,88.38 61.36,87.98 65.1,87.98 65.68,87.4 65.68,87.05 v1(65.95,86.78)
  BOTTOM w0.109: U37.18 46.62,78.21 46.74,78.09 46.91,78.09 47.18,78.37 47.18,81.24 v6(46.92,81.49) ; U43.45 65.58,87.53 65.66,87.46 65.66,87.07 v1(65.95,86.78)
USB0_VBUS2: length 10.4
  TOP w0.381: v1(46.2,98.98) 45.85,98.63 C274.1
  L05_SIG w0.381: U44.10 53.01,104.65 ; U44.10 52.38,104.46 ; U44.10 52.38,103.18 ; U44.10 53.65,104.46 ; U44.10 53.01,102.99 ; U44.10 53.65,103.18 ; U44.10 52.18,103.82 ; U44.10 53.84,103.82
  BOTTOM w0.254: X6.6 v1(46.92,96.72)
  BOTTOM w0.381: v1(39.87,98.25) U45.7
  vias: v1(39.87,99.4)
USB0_VBUS3: length 10.5
  TOP w0.381: C272.1 48.87,98.62 v1(48.46,99.03)
  L10_SIG w0.381: U44.1 53.65,106.38 ; U44.1 53.84,107.02 ; U44.1 53.01,107.85 ; U44.1 53.65,107.66 ; U44.1 53.01,106.19 ; U44.1 52.38,107.66 ; U44.1 52.18,107.02 ; U44.1 52.38,106.38
  BOTTOM w0.254: X5.6 v1(49.23,96.74)
  BOTTOM w0.381: U45.6 39.22,97.79 v1(38.75,98.25)
  vias: v1(38.75,99.4)
USB_JTAG_DM_N: length 12.3
  TOP w0.109: J4.2 v3(54.39,5.23) ; X1.2 55.73,7.49 55.73,6.92 v1(56,6.64)
  L03_SIG w0.109: v3(54.39,5.23) 54.59,5.43 54.59,5.88 54.4,6.07 54.4,7.06 54.96,7.61 55.4,7.61 55.73,7.28 55.73,6.92 v1(56,6.64)
  BOTTOM w0.109: U24.7 55.86,11.05 55.73,10.93 55.73,6.91 v1(56,6.64)
USB_JTAG_DM_P: length 12.2
  TOP w0.109: v1(55.2,6.64) 55.48,6.92 55.48,7.49 X1.1 ; J4.3 v3(55.04,5.23)
  L03_SIG w0.109: v3(55.04,5.23) 54.84,5.42 54.84,5.99 54.66,6.17 54.66,6.95 55.06,7.36 55.29,7.36 55.47,7.18 55.47,6.92 v1(55.2,6.64)
  BOTTOM w0.109: U24.8 55.36,11.05 55.48,10.93 55.48,8.01 55.35,7.87 55.05,7.87 54.91,7.74 54.91,7.55 55.05,7.41 55.35,7.41 55.48,7.28 55.48,6.92 v1(55.2,6.64)
USB_JTAG_FLTR: length 4.1
  TOP w0.381: 52.02,8.95 C87.1 52.5,8.47 ; R40.1 43.43,16.65 v1(43.99,16.09) ; 50.52,8.47 C89.1 51,8.95
  vias: v1(44.37,13.55) v1(44.37,12.41) v1(50.97,9.44) v1(51.99,9.44) v1(53.13,9.44)
USB_JTAG_VBUS: length 5.5
  TOP w0.381: C88.1 58.74,8.63 58.31,9.06 v1(57.9,9.06)
  L03_SIG w0.508: v1(57.9,9.06) 57.18,9.77 56,9.77 v1(54.78,8.56)
USB_JTAG_VCORE: length 10
  TOP w0.381: v1(52.96,10.69) 52.97,10.69 53.36,11.07 C96.1 ; C95.1 v1(62.23,21.46) ; C97.1 v1(62.1,13.96) ; C98.1 v1(53.36,24.81)
  BOTTOM w0.254: U24.49 v1(62.23,21.46) ; U24.64 v1(62.1,13.96) ; U24.37 v1(53.36,24.81) ; v1(52.96,10.69) 53.08,10.69 53.36,10.96 U24.12
USB_JTAG_VPHY: length 4.1
  TOP w0.381: v1(57.36,13.56) 57.36,12.99 C83.1 ; C82.1 57.24,16.28 ; C82.1 57.24,15.32 ; C82.1 56.77,15.8
  BOTTOM w0.254: U24.4 v1(57.36,13.56)
USB_JTAG_VPLL: length 3.8
  TOP w0.381: C84.1 55.11,10.59 v1(54.86,10.33) ; 50.02,10.27 C85.1 49.54,10.75
  BOTTOM w0.254: U24.9 v1(54.86,10.33)
  vias: v1(50.34,10.27) v1(50.47,11.25)
USB_PWRD_VCCIO: length 40.2
  TOP w0.178: v1(48.33,26.19) 48.77,25.75 U25.7 ; U25.10 47.89,24.35 v1(47.31,23.77)
  TOP w0.254: v1(44.12,19.86) 44.49,19.49 D25.1 ; D24.1 38.19,19.8 v1(37.81,20.17) ; R266.1 40.1,19.26 v1(40.35,19.51) ; R233.1 v1(54.91,20.11) R234.1 ; v1(47.42,19.48) 47.16,19.22 R765.1
  TOP w0.381: C94.1 v1(68.84,21.96) ; v1(62.23,20.6) 62.09,20.46 C105.1 ; v1(45.37,25.11) 44.91,25.57 C93.1 ; R74.1 v1(65.03,13.9) ; C100.1 62,17.96 v1(62.23,18.18) ; R76.1 v1(67.57,16.56) ; C101.1 51.23,21 v1(51.19,20.96) ; R235.1 v1(54.65,15.55) ; R77.1 v1(68.84,16.56) ; C99.1 v1(55.86,24.81) ; R75.1 v1(52.36,13.64)
  BOTTOM w0.178: U64.7 43.92,27.08 v1(44.35,27.52) ; U64.10 44.8,25.68 v1(45.37,25.11) ; U22.4 39.66,28.06 39.78,27.94 v1(40.27,27.94) 40.27,28.13 39.94,28.46 U22.3
  BOTTOM w0.254: U24.50 61.86,20.96 v1(62.23,20.6) ; U24.31 v1(51.19,20.96) ; U24.20 v1(48.13,15.46) ; U24.56 62,17.96 v1(62.23,18.18) ; v1(37.81,20.17) 38.19,19.8 R267.1 ; R764.1 45.13,19.48 44.75,19.86 v1(44.12,19.86) ; U24.42 v1(55.86,24.81)
  BOTTOM w0.381: 39.51,14.57 R36.1 38.95,14.01 ; C90.1 47.84,24.3 v1(47.31,23.77) ; 38.02,12.08 C44.1 38.58,12.64 ; C102.1 48.11,15.48 v1(48.13,15.46) ; U26.8 v1(68.84,21.96) ; v1(40.27,27.94) 40.33,27.88 C80.1
  vias: v1(38.94,13.28) v1(39.44,13.92) v1(40.03,13.35) v1(46.78,11.73) v1(46.78,10.59) v1(58.85,19.48) v1(58.85,18.33)
UTIL_3V3: length 242.9
  TOP w0.381: DS4.2 v1(3.61,19.95) ; DS7.2 v1(3.61,37.73) ; DS8.2 3.61,35.09 v1(3.43,35.28) ; DS9.2 v1(137.08,16.56) ; v1(3.81,30.27) 3.61,30.07 DS1.2 ; DS2.2 v1(3.61,25.03) ; DS3.2 v1(3.61,22.49) ; DS5.2 v1(3.61,17.41) ; DS6.2 v1(3.61,27.57)
  L05_SIG w0.508: v8(2.67,79.1) 2.63,79.15 2.63,83.31 2.92,83.61 2.92,86.18 1.77,87.33 1.77,91.21 0.96,92.02 0.96,106.13 2.23,107.4 2.23,108.61 2.23,108.61 v6(2.23,109.24)
  L10_SIG w0.635: v1(137.08,16.56) 137.08,15.41 129.46,7.79 129.46,3.6 127.71,1.85 69.95,1.85 63.39,8.4 59.94,8.4 59.2,7.67 49.86,7.67 49.45,7.26 12.32,7.26 10.11,9.47 10.11,14.64 7.42,17.32 6.02,17.32 5.58,16.88 4.83,16.88 4.3,17.41 v1(3.61,17.41)
  L12_SIG w0.508: v8(2.67,79.1) 2.67,78.3 3.43,77.54 4.06,77.54 5.76,75.84 5.76,75.46 7.08,74.14 7.08,72.61 5.07,70.6 5.07,66.03 3.86,64.82 3.86,58.77 3.3,58.21 3.3,46.63 4.51,45.42 4.51,42.11 3.87,41.46 3.87,40.3 v2(4.87,39.29)
  BOTTOM w0.381: 7.64,41.17 C41.1 8.19,40.61 ; U14.10 2.34,78.77 v8(2.67,79.1) 2.64,79.13 C49.1 ; R39.1 8.19,39.59
  BOTTOM w0.457: R260.1 v6(2.23,109.24)
  vias: v8(7.84,41.32) v8(8.71,39.72) v8(8.84,41.37) v8(9.85,41.39) v8(9.83,39.74)
VISOIN_RS485: length 2.7
  BOTTOM w0.381: v1(117.18,85.3) 116.96,85.52 C604.1 C603.1 v1(117.14,86.52)
  vias: v1(112.55,79)
VISOOUT_RS485: length 1.3
  BOTTOM w0.381: v1(113.6,82) 114.01,82.42 R534.2
  vias: v1(112.6,81.27) v1(113.6,80.8)
VREF_DCLINK: length 8.5
  TOP w0.381: R736.2 68.29,37.92 66.82,36.44 65.27,36.44
  BOTTOM w0.381: U114.3 64.75,37.39 v1(65.13,37.01) ; U114.6 64.75,35.44 v1(65.13,35.83)
VREF_PA: length 9.4
  TOP w0.381: R730.2 68.5,46.02 67.1,44.62 65.3,44.62
  BOTTOM w0.381: U108.6 64.75,43.61 v1(65.13,43.99) ; v1(65.13,45.18) 64.75,45.56 U108.3
VREF_PA_R: length 11.1
  TOP w0.381: v1(69.78,50.45) 69.4,50.07 R731.2 R730.1 ; C806.1 70.43,45.7 v1(70.25,45.51)
  L10_SIG w0.381: v1(69.78,50.45) 69.24,49.9 69.24,46.53 v1(70.25,45.51)
  BOTTOM w0.381: v1(70.25,45.51) 70.43,45.7 C806.1 ; U123.5 v1(69.78,50.45)
VREF_PB: length 9
  TOP w0.381: 65.27,52.8 66.87,52.8 68.5,54.43 R732.2
  BOTTOM w0.381: U110.3 64.75,53.73 v1(65.13,53.35) ; v1(65.13,52.16) 64.75,51.78 U110.6
VREF_PB_R: length 11.1
  TOP w0.381: v1(70.25,53.39) 70.43,53.57 C807.1 ; v1(69.78,58.32) 69.4,57.94 R733.2 R732.1
  L10_SIG w0.381: v1(69.78,58.32) 69.26,57.8 69.26,54.38 v1(70.25,53.39)
  BOTTOM w0.381: v1(70.25,53.39) 70.43,53.57 C807.1 ; U124.5 v1(69.78,58.32)
VREF_PC: length 8.3
  TOP w0.381: 65.3,60.9 66.9,60.9 68.5,62.51 R734.2
  BOTTOM w0.381: U112.3 64.75,61.9 v1(65.13,61.52) ; U112.6 64.75,59.95 v1(65.13,60.33)
VREF_PC_R: length 11
  TOP w0.381: v1(69.78,65.75) 69.4,65.36 R735.2 R734.1 ; v1(70.25,60.81) 70.43,61 C808.1
  L10_SIG w0.381: v1(70.25,60.81) 69.31,61.75 69.31,65.27 v1(69.78,65.75)
  BOTTOM w0.381: U125.5 v1(69.78,65.75) ; v1(70.25,60.81) 70.43,61 C808.1
WATCHDOG_CRST: length 3
  BOTTOM w0.13: U13.4 3.15,84.38 R49.2 C52.1
WATCHDOG_CWD: length 3.4
  BOTTOM w0.13: U13.2 4.15,85.27 R48.2 C51.1
WATCHDOG_SET0: length 2.9
  BOTTOM w0.13: R51.1 R47.2 U13.3
WATCHDOG_SET1: length 2.9
  BOTTOM w0.13: R46.2 R50.1 2.65,90.65 U13.6
WATCHDOG_WDO_B: length 105.6
  L05_SIG w0.102: v1(41.09,56.21) 38.63,53.74 34.59,53.74 34.03,54.3 20.53,54.3 17.35,57.49 12.51,57.49 11.78,58.21 11.78,65.55 9.98,67.36 9.98,73.53 8.51,75 8.51,84.91 4.19,89.23 v1(4.19,89.76)
  L10_SIG w0.102: J1.2 41.84,21.95 44.55,24.66 44.55,26.57 44.88,26.9 44.88,28.9 43.55,30.23 43.55,48.7 41.09,51.15 v1(41.09,56.21)
  BOTTOM w0.13: v1(4.19,89.76) 3.65,89.22 U13.8
Y_RS485: length 31.5
  TOP w0.381: U95.17 119.09,87.41 120.21,88.53 120.97,88.53 124.44,92 124.44,99.55 125.54,100.64 v1(127.1,100.64) 127.55,100.64 J22.4
  BOTTOM w0.381: 125,100.64 v1(127.1,100.64)
Z_RS485: length 26.8
  TOP w0.381: J22.3 130.13,98.22 v1(127.1,98.22) 127.1,95.98 126.61,95.5 126.61,91.76 124.07,89.22 123.37,89.22 120.36,86.21 U95.18
  BOTTOM w0.381: v1(127.1,98.22) 126.57,98.74 D23.1
N1366089: length 9
  BOTTOM w0.508: D2.2 6.97,105.7 7.11,105.84 Q18.3 ; D2.2 5.24,104.47 4.57,103.8 L9.2 ; D2.2 6.97,103.68 6.84,103.55 C208.2
N1766802: length 3.2
  BOTTOM w0.178: R33.1 19.75,20.64 18.39,22 U6.2
